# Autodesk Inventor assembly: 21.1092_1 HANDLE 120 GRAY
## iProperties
Created: 2007-03
Part Number: 21.1092_1 HANDLE 120 GRAY
Document SubType Name: Assembly
Designer: Andy Moles
Mass: 77.6416 g
Surface Area: 194.258 cm^2
Volume: 46.714 cm^3
Density: 1.66206 g/cm^3
Author: Andy Moles
